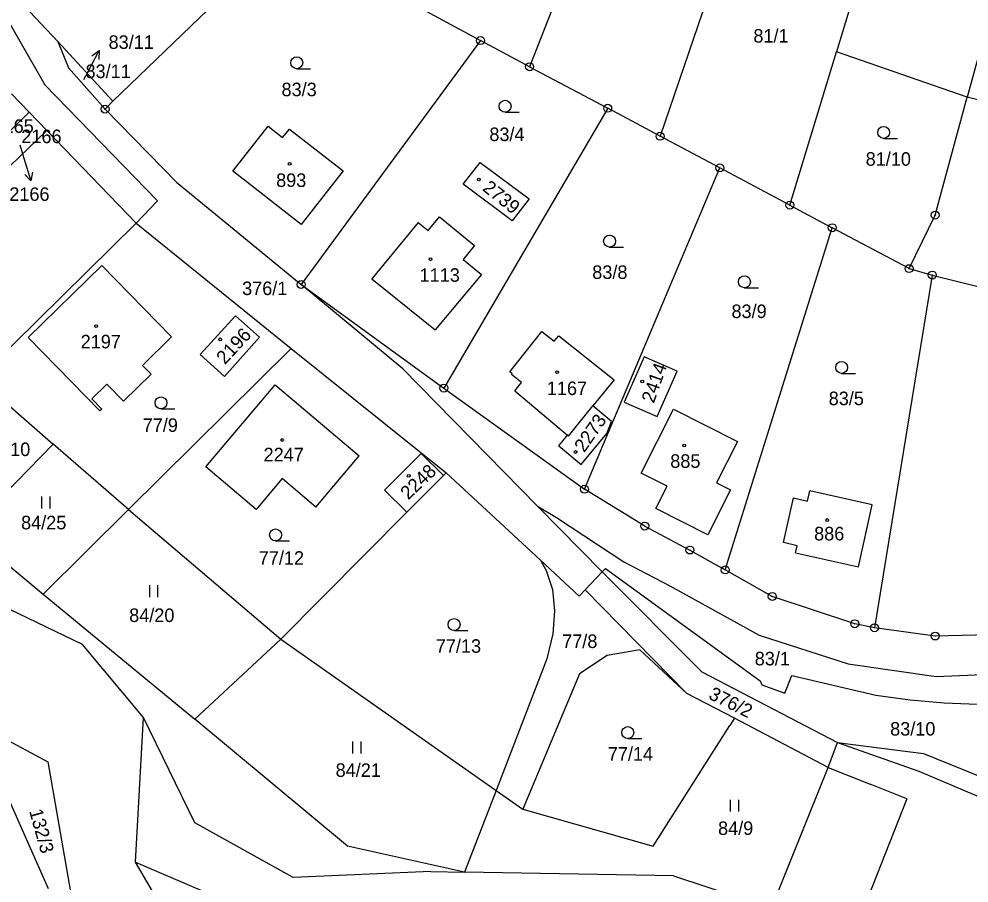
# Model space of a CAD drawing. Extents: x -735249 to -729401, y -1124843 to -1121828.
# Drawn here: x -734250.1 to -734130.6, y -1123331.7 to -1123223 of the extents above; entities that cross this region are included whole.
import ezdxf

# ---------------------------------------------------------------- set-up
doc = ezdxf.new("R2010")
doc.units = 0
for name, color, linetype in [('Vrstva 1', 7, 'Continuous'), ('Vrstva 16', 7, 'Continuous'), ('Vrstva 18', 7, 'Continuous'), ('Vrstva 19', 7, 'Continuous'), ('Vrstva 25', 7, 'Continuous'), ('Vrstva 4', 7, 'Continuous')]:
    doc.layers.add(name, color=color, linetype=linetype)

msp = doc.modelspace()

# ---------------------------------------------------------------- linework, layer by layer
at = {"layer": 'Vrstva 1'}
for points in [[(-734171.57, -1123192.57), (-734185.89, -1123229.04)], [(-734155.82, -1123197.73), (-734169.48, -1123237.78)], [(-734139.96, -1123202.94), (-734147.31, -1123227.18)], [(-734124.09, -1123208.07), (-734130.86, -1123232.89)], [(-734257.34, -1123213.05), (-734246.85, -1123231.31)], [(-734257.34, -1123213.05), (-734245.22, -1123225.89)], [(-734238.31, -1123233.36), (-734216.53, -1123212.44)], [(-734201.61, -1123220.55), (-734192.06, -1123225.76)], [(-734238.31, -1123233.36), (-734245.22, -1123225.89)], [(-734245.22, -1123225.89), (-734243.86, -1123229.2)], [(-734192.06, -1123225.76), (-734214.63, -1123256.42)], [(-734185.89, -1123229.04), (-734192.06, -1123225.76)], [(-734153.16, -1123246.45), (-734147.31, -1123227.18)], [(-734130.86, -1123232.89), (-734147.31, -1123227.18)], [(-734243.86, -1123229.2), (-734239.27, -1123234.38)], [(-734185.89, -1123229.04), (-734176.07, -1123234.27)], [(-734248.81, -1123234.76), (-734251.02, -1123232.46)], [(-734246.85, -1123231.31), (-734232.7, -1123245.9)], [(-734238.31, -1123233.36), (-734239.27, -1123234.38)], [(-734134.89, -1123247.7), (-734130.86, -1123232.89)], [(-734117.25, -1123236.28), (-734130.86, -1123232.89)], [(-734253.39, -1123239.18), (-734248.81, -1123234.76)], [(-734246.59, -1123237.06), (-734248.81, -1123234.76)], [(-734239.27, -1123234.38), (-734230.3, -1123243.56)], [(-734176.07, -1123234.27), (-734196.67, -1123269.44)], [(-734169.48, -1123237.78), (-734176.07, -1123234.27)], [(-734251.19, -1123241.49), (-734246.59, -1123237.06)], [(-734235.37, -1123248.7), (-734246.59, -1123237.06)], [(-734223.19, -1123242.18), (-734218.77, -1123236.52)], [(-734218.77, -1123236.52), (-734216.94, -1123237.95)], [(-734216.94, -1123237.95), (-734216.1, -1123236.88)], [(-734216.1, -1123236.88), (-734209.35, -1123242.14)], [(-734161.97, -1123241.77), (-734169.48, -1123237.78)], [(-734194.25, -1123243.82), (-734192.1, -1123241.08)], [(-734192.1, -1123241.08), (-734185.96, -1123245.65)], [(-734178.98, -1123282.16), (-734161.97, -1123241.77)], [(-734153.16, -1123246.45), (-734161.97, -1123241.77)], [(-734221.36, -1123243.61), (-734223.19, -1123242.18)], [(-734209.35, -1123242.14), (-734214.62, -1123248.88)], [(-734230.3, -1123243.56), (-734214.63, -1123256.42)], [(-734214.62, -1123248.88), (-734221.36, -1123243.61)], [(-734188.1, -1123248.41), (-734194.25, -1123243.82)], [(-734235.37, -1123248.7), (-734232.7, -1123245.9)], [(-734185.96, -1123245.65), (-734188.1, -1123248.41)], [(-734153.16, -1123246.45), (-734147.83, -1123249.29)], [(-734198.64, -1123249.65), (-734197.21, -1123247.9)], [(-734197.21, -1123247.9), (-734192.8, -1123251.53)], [(-734138.17, -1123254.43), (-734134.89, -1123247.7)], [(-734254.03, -1123267.05), (-734235.37, -1123248.7)], [(-734235.37, -1123248.7), (-734215.87, -1123264.46)], [(-734199.9, -1123248.61), (-734205.73, -1123255.69)], [(-734199.9, -1123248.61), (-734198.64, -1123249.65)], [(-734161.29, -1123292.3), (-734147.83, -1123249.29)], [(-734138.17, -1123254.43), (-734147.83, -1123249.29)], [(-734192.8, -1123251.53), (-734194.24, -1123253.27)], [(-734194.24, -1123253.27), (-734191.93, -1123255.18)], [(-734248.95, -1123263.09), (-734239.69, -1123254.03)], [(-734239.69, -1123254.03), (-734230.9, -1123263.01)], [(-734191.93, -1123255.18), (-734197.77, -1123262.14)], [(-734138.17, -1123254.43), (-734135.25, -1123255.23)], [(-734205.73, -1123255.69), (-734197.77, -1123262.14)], [(-734135.25, -1123255.23), (-734142.52, -1123299.57)], [(-734135.25, -1123255.23), (-734119.79, -1123259.05)], [(-734201.81, -1123267.02), (-734214.63, -1123256.42)], [(-734214.63, -1123256.42), (-734196.67, -1123269.44)], [(-734227.32, -1123265.24), (-734222.86, -1123260.35)], [(-734222.86, -1123260.35), (-734219.84, -1123263.06)], [(-734188.36, -1123267.42), (-734184.35, -1123262.32)], [(-734184.35, -1123262.32), (-734182.79, -1123263.56)], [(-734239.92, -1123272.31), (-734248.95, -1123263.09)], [(-734230.9, -1123263.01), (-734234.56, -1123266.59)], [(-734219.84, -1123263.06), (-734224.27, -1123267.98)], [(-734182.79, -1123263.56), (-734182.23, -1123262.86)], [(-734182.23, -1123262.86), (-734175.27, -1123268.41)], [(-734215.87, -1123264.46), (-734236.33, -1123284.72)], [(-734215.87, -1123264.46), (-734196.38, -1123280.09)], [(-734224.27, -1123267.98), (-734227.32, -1123265.24)], [(-734171.5, -1123265.51), (-734173.99, -1123271.21)], [(-734167.34, -1123267.33), (-734171.5, -1123265.51)], [(-734234.56, -1123266.59), (-734233.49, -1123267.68)], [(-734201.81, -1123267.02), (-734184.91, -1123284.27)], [(-734255.26, -1123268.24), (-734245.8, -1123276.48)], [(-734233.49, -1123267.68), (-734236.96, -1123271.08)], [(-734188.07, -1123267.65), (-734188.36, -1123267.42)], [(-734188.15, -1123267.75), (-734188.07, -1123267.65)], [(-734186.92, -1123268.74), (-734188.15, -1123267.75)], [(-734169.83, -1123273.03), (-734167.34, -1123267.33)], [(-734239.04, -1123268.96), (-734240.94, -1123270.81)], [(-734236.96, -1123271.08), (-734239.04, -1123268.96)], [(-734226.59, -1123279.36), (-734217.88, -1123269.03)], [(-734217.88, -1123269.03), (-734207.31, -1123277.95)], [(-734196.67, -1123269.44), (-734178.98, -1123282.16)], [(-734187.76, -1123269.8), (-734186.92, -1123268.74)], [(-734175.27, -1123268.41), (-734177.92, -1123271.68)], [(-734187.76, -1123269.8), (-734181.11, -1123275.38)], [(-734240.94, -1123270.81), (-734239.69, -1123272.08)], [(-734181, -1123275.48), (-734177.92, -1123271.68)], [(-734175.6, -1123273.63), (-734177.92, -1123271.68)], [(-734173.99, -1123271.21), (-734169.83, -1123273.03)], [(-734239.69, -1123272.08), (-734239.92, -1123272.31)], [(-734171.87, -1123280.12), (-734167.8, -1123272.08)], [(-734167.8, -1123272.08), (-734159.76, -1123276.15)], [(-734176.17, -1123275.17), (-734175.6, -1123273.63)], [(-734182.21, -1123276.69), (-734181.11, -1123275.38)], [(-734181, -1123275.48), (-734181.11, -1123275.38)], [(-734179.42, -1123279.04), (-734176.17, -1123275.17)], [(-734245.8, -1123276.48), (-734256.54, -1123287.49)], [(-734236.33, -1123284.72), (-734245.8, -1123276.48)], [(-734182.21, -1123276.69), (-734179.42, -1123279.04)], [(-734159.76, -1123276.15), (-734162.39, -1123281.35)], [(-734199.53, -1123277.65), (-734204.12, -1123282.28)], [(-734199.53, -1123277.65), (-734196.73, -1123280.44)], [(-734212.75, -1123284.4), (-734207.31, -1123277.95)], [(-734220.26, -1123284.69), (-734226.59, -1123279.36)], [(-734196.73, -1123280.44), (-734196.38, -1123280.09)], [(-734196.38, -1123280.09), (-734184.51, -1123291.08)], [(-734168.59, -1123281.78), (-734171.87, -1123280.12)], [(-734217, -1123280.82), (-734220.26, -1123284.69)], [(-734212.75, -1123284.4), (-734217, -1123280.82)], [(-734196.73, -1123280.44), (-734201.32, -1123285.06)], [(-734162.39, -1123281.35), (-734160.61, -1123282.25)], [(-734204.12, -1123282.28), (-734201.32, -1123285.06)], [(-734171.41, -1123286.79), (-734178.98, -1123282.16)], [(-734170.02, -1123284.59), (-734168.59, -1123281.78)], [(-734160.61, -1123282.25), (-734163.47, -1123287.91)], [(-734150.96, -1123283.64), (-734150.67, -1123282.35)], [(-734142.83, -1123284.1), (-734150.67, -1123282.35)], [(-734153.98, -1123288.87), (-734152.7, -1123283.25)], [(-734152.7, -1123283.25), (-734150.96, -1123283.64)], [(-734247.04, -1123295.34), (-734236.33, -1123284.72)], [(-734236.33, -1123284.72), (-734217.15, -1123301.01)], [(-734184.91, -1123284.27), (-734182.51, -1123285.72)], [(-734184.91, -1123284.27), (-734176.75, -1123292.55)], [(-734163.47, -1123287.91), (-734170.02, -1123284.59)], [(-734144.53, -1123291.91), (-734142.83, -1123284.1)], [(-734217.15, -1123301.01), (-734201.32, -1123285.06)], [(-734182.51, -1123285.72), (-734174.03, -1123291.27)], [(-734171.41, -1123286.79), (-734165.73, -1123289.8)], [(-734256.54, -1123287.49), (-734247.04, -1123295.34)], [(-734165.73, -1123289.8), (-734161.29, -1123292.3)], [(-734152.24, -1123289.27), (-734153.98, -1123288.87)], [(-734152.44, -1123290.16), (-734152.24, -1123289.27)], [(-734152.44, -1123290.16), (-734144.53, -1123291.91)], [(-734184.51, -1123291.08), (-734183.79, -1123292.36)], [(-734184.51, -1123291.08), (-734179.65, -1123295.61)], [(-734176.75, -1123292.55), (-734176.34, -1123292.12)], [(-734176.34, -1123292.12), (-734156.89, -1123306.24)], [(-734174.03, -1123291.27), (-734168.25, -1123294.32)], [(-734183.79, -1123292.36), (-734183.02, -1123294.76)], [(-734178.89, -1123294.81), (-734176.75, -1123292.55)], [(-734176.75, -1123292.55), (-734164.25, -1123305.13)], [(-734155.37, -1123295.64), (-734161.29, -1123292.3)], [(-734168.25, -1123294.32), (-734157.01, -1123300.51)], [(-734247.04, -1123295.34), (-734228, -1123311.08)], [(-734183.02, -1123294.76), (-734182.75, -1123297.43)], [(-734179.65, -1123295.61), (-734178.89, -1123294.81)], [(-734178.89, -1123294.81), (-734166.1, -1123307.82)], [(-734145, -1123299.07), (-734155.37, -1123295.64)], [(-734242.12, -1123301.67), (-734251.23, -1123297.26)], [(-734182.75, -1123297.43), (-734182.98, -1123300.35)], [(-734142.52, -1123299.57), (-734145, -1123299.07)], [(-734182.98, -1123300.35), (-734183.73, -1123303.5)], [(-734157.01, -1123300.51), (-734145.85, -1123304.09)], [(-734134.89, -1123300.61), (-734142.52, -1123299.57)], [(-734123.08, -1123300.32), (-734134.89, -1123300.61)], [(-734234.45, -1123310.87), (-734242.12, -1123301.67)], [(-734228, -1123311.08), (-734217.15, -1123301.01)], [(-734217.15, -1123301.01), (-734190.11, -1123320.05)], [(-734172.04, -1123302.34), (-734176.12, -1123303.05)], [(-734166.1, -1123307.82), (-734172.04, -1123302.34)], [(-734183.73, -1123303.5), (-734190.11, -1123320.05)], [(-734176.12, -1123303.05), (-734179.61, -1123305.37)], [(-734145.85, -1123304.09), (-734134.75, -1123305.68)], [(-734164.25, -1123305.13), (-734147.16, -1123313.99)], [(-734134.75, -1123305.68), (-734121.97, -1123305.16)], [(-734179.61, -1123305.37), (-734186.75, -1123322.38)], [(-734156.89, -1123306.24), (-734156.68, -1123306.73)], [(-734153.8, -1123307.79), (-734152.91, -1123305.57)], [(-734152.91, -1123305.57), (-734142.34, -1123308.04)], [(-734156.68, -1123306.73), (-734153.8, -1123307.79)], [(-734160.14, -1123310.95), (-734166.1, -1123307.82)], [(-734142.34, -1123308.04), (-734138.04, -1123308.65)], [(-734138.04, -1123308.65), (-734133.77, -1123309.02)], [(-734133.77, -1123309.02), (-734129.56, -1123309.17)], [(-734235.46, -1123329.05), (-734234.45, -1123310.87)], [(-734227.98, -1123324.11), (-734234.45, -1123310.87)], [(-734208.78, -1123327.01), (-734228, -1123311.08)], [(-734160.14, -1123310.95), (-734160.71, -1123311.84)], [(-734148.33, -1123317.15), (-734160.14, -1123310.95)], [(-734170.33, -1123327.04), (-734160.71, -1123311.84)], [(-734252.57, -1123313.14), (-734246.48, -1123316.44)], [(-734254.21, -1123314.84), (-734246.41, -1123332.36)], [(-734148.33, -1123317.15), (-734147.16, -1123313.99)], [(-734147.16, -1123313.99), (-734136.96, -1123317.6)], [(-734147.16, -1123313.99), (-734136.36, -1123315.39)], [(-734136.36, -1123315.39), (-734121.78, -1123321.31)], [(-734246.48, -1123316.44), (-734242.23, -1123340.7)], [(-734155.49, -1123334.83), (-734148.33, -1123317.15)], [(-734136.96, -1123317.6), (-734122.54, -1123323.74)], [(-734190.11, -1123320.05), (-734194.06, -1123330.29)], [(-734190.11, -1123320.05), (-734186.75, -1123322.38)], [(-734186.75, -1123322.38), (-734170.33, -1123327.04)], [(-734215.61, -1123330.96), (-734227.98, -1123324.11)], [(-734194.06, -1123330.29), (-734208.78, -1123327.01)], [(-734226.76, -1123343.82), (-734235.46, -1123329.05)], [(-734235.46, -1123329.05), (-734218.93, -1123336.13)], [(-734198.31, -1123330.22), (-734215.61, -1123330.96)], [(-734198.31, -1123330.22), (-734194.06, -1123330.29)], [(-734167.81, -1123330.75), (-734194.06, -1123330.29)], [(-734167.81, -1123330.75), (-734155.49, -1123334.83)]]:
    msp.add_lwpolyline(points, dxfattribs=at)
at = {"layer": 'Vrstva 16'}
for points in [[(-734241.93, -1123230.67), (-734241.41, -1123229.66)], [(-734250, -1123238.85), (-734249.48, -1123240.53)]]:
    msp.add_lwpolyline(points, dxfattribs=at)
at = {"layer": 'Vrstva 25'}
for points in [[(-734241.41, -1123229.66), (-734240.03, -1123226.997)], [(-734240.934, -1123227.655), (-734240.03, -1123226.997), (-734240.046, -1123228.115)], [(-734215.17, -1123229.29), (-734213.42, -1123229.29)], [(-734188.97, -1123234.76), (-734187.22, -1123234.76)], [(-734141.37, -1123238.05), (-734139.62, -1123238.05)], [(-734249.48, -1123240.53), (-734248.598, -1123243.397)], [(-734248.415, -1123242.294), (-734248.598, -1123243.397), (-734249.37, -1123242.588)], [(-734175.83, -1123251.72), (-734174.08, -1123251.72)], [(-734158.87, -1123256.83), (-734157.12, -1123256.83)], [(-734146.65, -1123267.59), (-734144.9, -1123267.59)], [(-734232.24, -1123272.05), (-734230.49, -1123272.05)], [(-734247.217, -1123284.565), (-734247.217, -1123283.065)], [(-734246.183, -1123284.565), (-734246.183, -1123283.065)], [(-734217.84, -1123288.65), (-734216.09, -1123288.65)], [(-734233.657, -1123295.715), (-734233.657, -1123294.215)], [(-734232.623, -1123295.715), (-734232.623, -1123294.215)], [(-734195.39, -1123299.92), (-734193.64, -1123299.92)], [(-734173.54, -1123313.5), (-734171.79, -1123313.5)], [(-734208.097, -1123315.385), (-734208.097, -1123313.885)], [(-734207.063, -1123315.385), (-734207.063, -1123313.885)], [(-734160.607, -1123322.685), (-734160.607, -1123321.185)], [(-734159.573, -1123322.685), (-734159.573, -1123321.185)]]:
    msp.add_lwpolyline(points, dxfattribs=at)
for centre, radius in [((-734192.06, -1123225.76), 0.5), ((-734192.06, -1123225.76), 0.032), ((-734215.17, -1123228.54), 0.75), ((-734185.89, -1123229.04), 0.5), ((-734185.89, -1123229.04), 0.032), ((-734188.97, -1123234.01), 0.75), ((-734239.27, -1123234.38), 0.5), ((-734239.27, -1123234.38), 0.032), ((-734176.07, -1123234.27), 0.5), ((-734176.07, -1123234.27), 0.032), ((-734141.37, -1123237.3), 0.75), ((-734169.48, -1123237.78), 0.5), ((-734169.48, -1123237.78), 0.032), ((-734216.06, -1123241.26), 0.175), ((-734161.97, -1123241.77), 0.5), ((-734161.97, -1123241.77), 0.032), ((-734192.28, -1123243.22), 0.175), ((-734153.16, -1123246.45), 0.5), ((-734153.16, -1123246.45), 0.032), ((-734134.89, -1123247.7), 0.5), ((-734134.89, -1123247.7), 0.032), ((-734147.83, -1123249.29), 0.5), ((-734175.83, -1123250.97), 0.75), ((-734147.83, -1123249.29), 0.032), ((-734198.35, -1123253.25), 0.175), ((-734138.17, -1123254.43), 0.5), ((-734138.17, -1123254.43), 0.032), ((-734135.25, -1123255.23), 0.5), ((-734214.63, -1123256.42), 0.5), ((-734158.87, -1123256.08), 0.75), ((-734135.25, -1123255.23), 0.032), ((-734214.63, -1123256.42), 0.032), ((-734240.39, -1123261.67), 0.175), ((-734224.79, -1123263.32), 0.175), ((-734146.65, -1123266.84), 0.75), ((-734182.41, -1123267.43), 0.175), ((-734196.67, -1123269.44), 0.5), ((-734196.67, -1123269.44), 0.032), ((-734171.72, -1123268.62), 0.175), ((-734232.24, -1123271.3), 0.75), ((-734216.99, -1123275.97), 0.175), ((-734166.44, -1123276.66), 0.175), ((-734180.1, -1123277.48), 0.175), ((-734201.09, -1123280.47), 0.175), ((-734178.98, -1123282.16), 0.5), ((-734178.98, -1123282.16), 0.032), ((-734148.48, -1123286.03), 0.175), ((-734217.84, -1123287.9), 0.75), ((-734171.41, -1123286.79), 0.5), ((-734171.41, -1123286.79), 0.032), ((-734165.73, -1123289.8), 0.5), ((-734165.73, -1123289.8), 0.032), ((-734161.29, -1123292.3), 0.5), ((-734161.29, -1123292.3), 0.032), ((-734155.37, -1123295.64), 0.5), ((-734155.37, -1123295.64), 0.032), ((-734195.39, -1123299.17), 0.75), ((-734145, -1123299.07), 0.5), ((-734145, -1123299.07), 0.032), ((-734142.52, -1123299.57), 0.5), ((-734142.52, -1123299.57), 0.032), ((-734134.89, -1123300.61), 0.5), ((-734134.89, -1123300.61), 0.032), ((-734173.54, -1123312.75), 0.75)]:
    msp.add_circle(centre, radius, dxfattribs=at)
at = {"layer": 'Vrstva 4'}
for points in [[(-734148.33, -1123317.15), (-734143.07, -1123319.25)], [(-734138.46, -1123321.08), (-734143.07, -1123319.25)], [(-734138.46, -1123321.08), (-734145.46, -1123338.85)]]:
    msp.add_lwpolyline(points, dxfattribs=at)

# ---------------------------------------------------------------- texts
at = {"layer": 'Vrstva 16'}
for s, p in [('83/11', (-734238.83, -1123226.8)), ('2166', (-734251.316, -1123245.91))]:
    msp.add_text(s, height=1.7, dxfattribs=at).set_placement(p)
at = {"layer": 'Vrstva 18'}
for s, p in [('81/1', (-734157.75, -1123226.01)), ('83/11', (-734241.73, -1123230.47)), ('83/3', (-734217.08, -1123232.75)), ('83/4', (-734190.95, -1123238.39)), ('81/10', (-734143.63, -1123241.49)), ('83/8', (-734178.01, -1123255.72)), ('376/1', (-734222.04, -1123257.75)), ('83/9', (-734160.5, -1123260.64)), ('83/5', (-734148.28, -1123271.59)), ('77/9', (-734234.54, -1123274.95)), ('84/10', (-734254.37, -1123277.99)), ('84/25', (-734249.83, -1123287.2)), ('77/12', (-734219.94, -1123291.65)), ('84/20', (-734236.24, -1123298.85)), ('77/8', (-734181.79, -1123302.12)), ('77/13', (-734197.68, -1123302.72)), ('83/1', (-734157.58, -1123304.3)), ('83/10', (-734140.55, -1123313.13)), ('77/14', (-734176.05, -1123316.28)), ('84/21', (-734210.28, -1123318.32)), ('84/9', (-734162.19, -1123325.62))]:
    msp.add_text(s, height=1.7, dxfattribs=at).set_placement(p)
for s, rotation, p in [('376/2', 333.70265, (-734163.503, -1123308.44)), ('132/3', 285.80227, (-734248.834, -1123322.607))]:
    msp.add_text(s, height=1.7, rotation=rotation, dxfattribs=at).set_placement(p)
at = {"layer": 'Vrstva 19'}
for s, p in [('2165', (-734253.3, -1123237.36)), ('2166', (-734249.8, -1123238.65)), ('893', (-734217.76, -1123244.16)), ('1113', (-734199.72, -1123256.08)), ('2197', (-734242.34, -1123264.45)), ('1167', (-734183.72, -1123270.32)), ('2247', (-734219.34, -1123278.65)), ('885', (-734168.2, -1123279.47)), ('886', (-734150.11, -1123288.59))]:
    msp.add_text(s, height=1.7, dxfattribs=at).set_placement(p)
for s, rotation, p in [('2739', 321.20256, (-734191.929, -1123244.5)), ('2196', 47.20038, (-734224.2, -1123266.568)), ('2414', 70.50056, (-734170.271, -1123271.435)), ('2273', 55.30044, (-734179.01, -1123277.632)), ('2248', 43.60035, (-734201.144, -1123283.568))]:
    msp.add_text(s, height=1.7, rotation=rotation, dxfattribs=at).set_placement(p)

doc.saveas('drawing.dxf')
